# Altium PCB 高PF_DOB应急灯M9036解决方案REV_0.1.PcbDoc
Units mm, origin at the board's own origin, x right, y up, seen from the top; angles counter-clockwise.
Board outline 152.4 x 101.6 mm, 2 copper layers (Top Layer, Bottom Layer); 44 components, 28 nets, 116 pads, 0 vias.
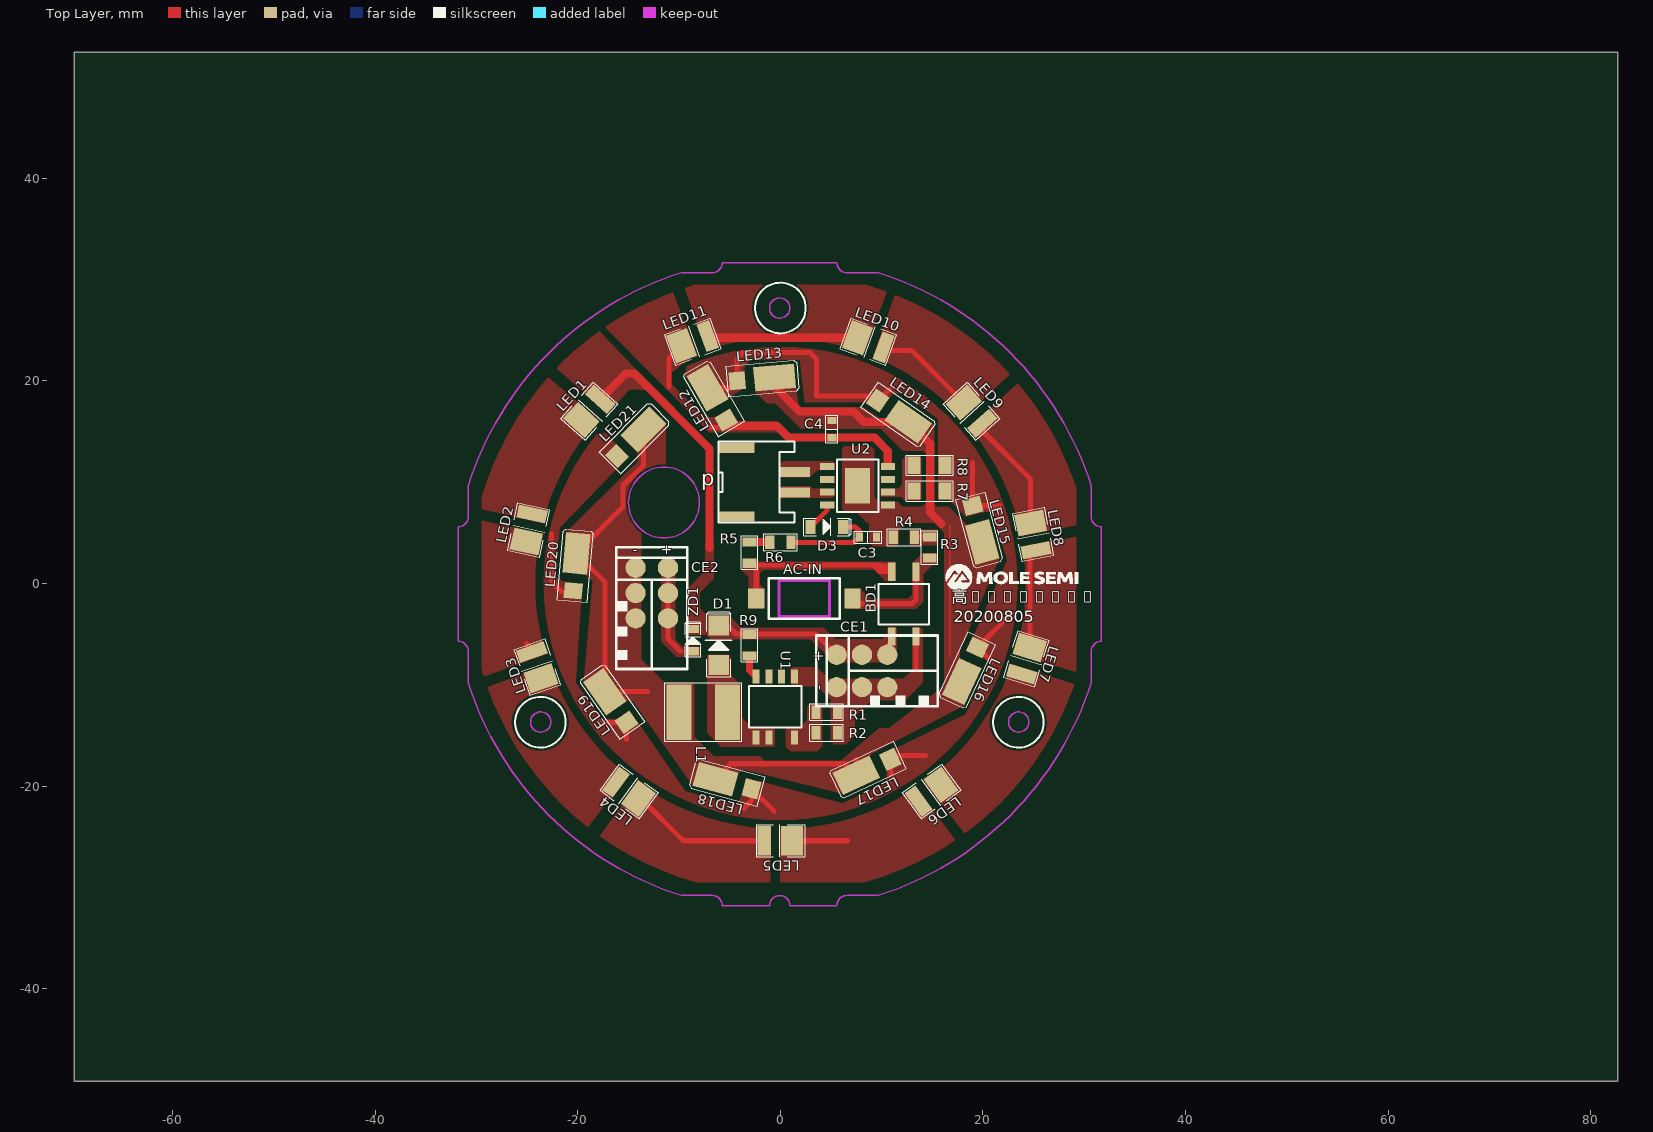
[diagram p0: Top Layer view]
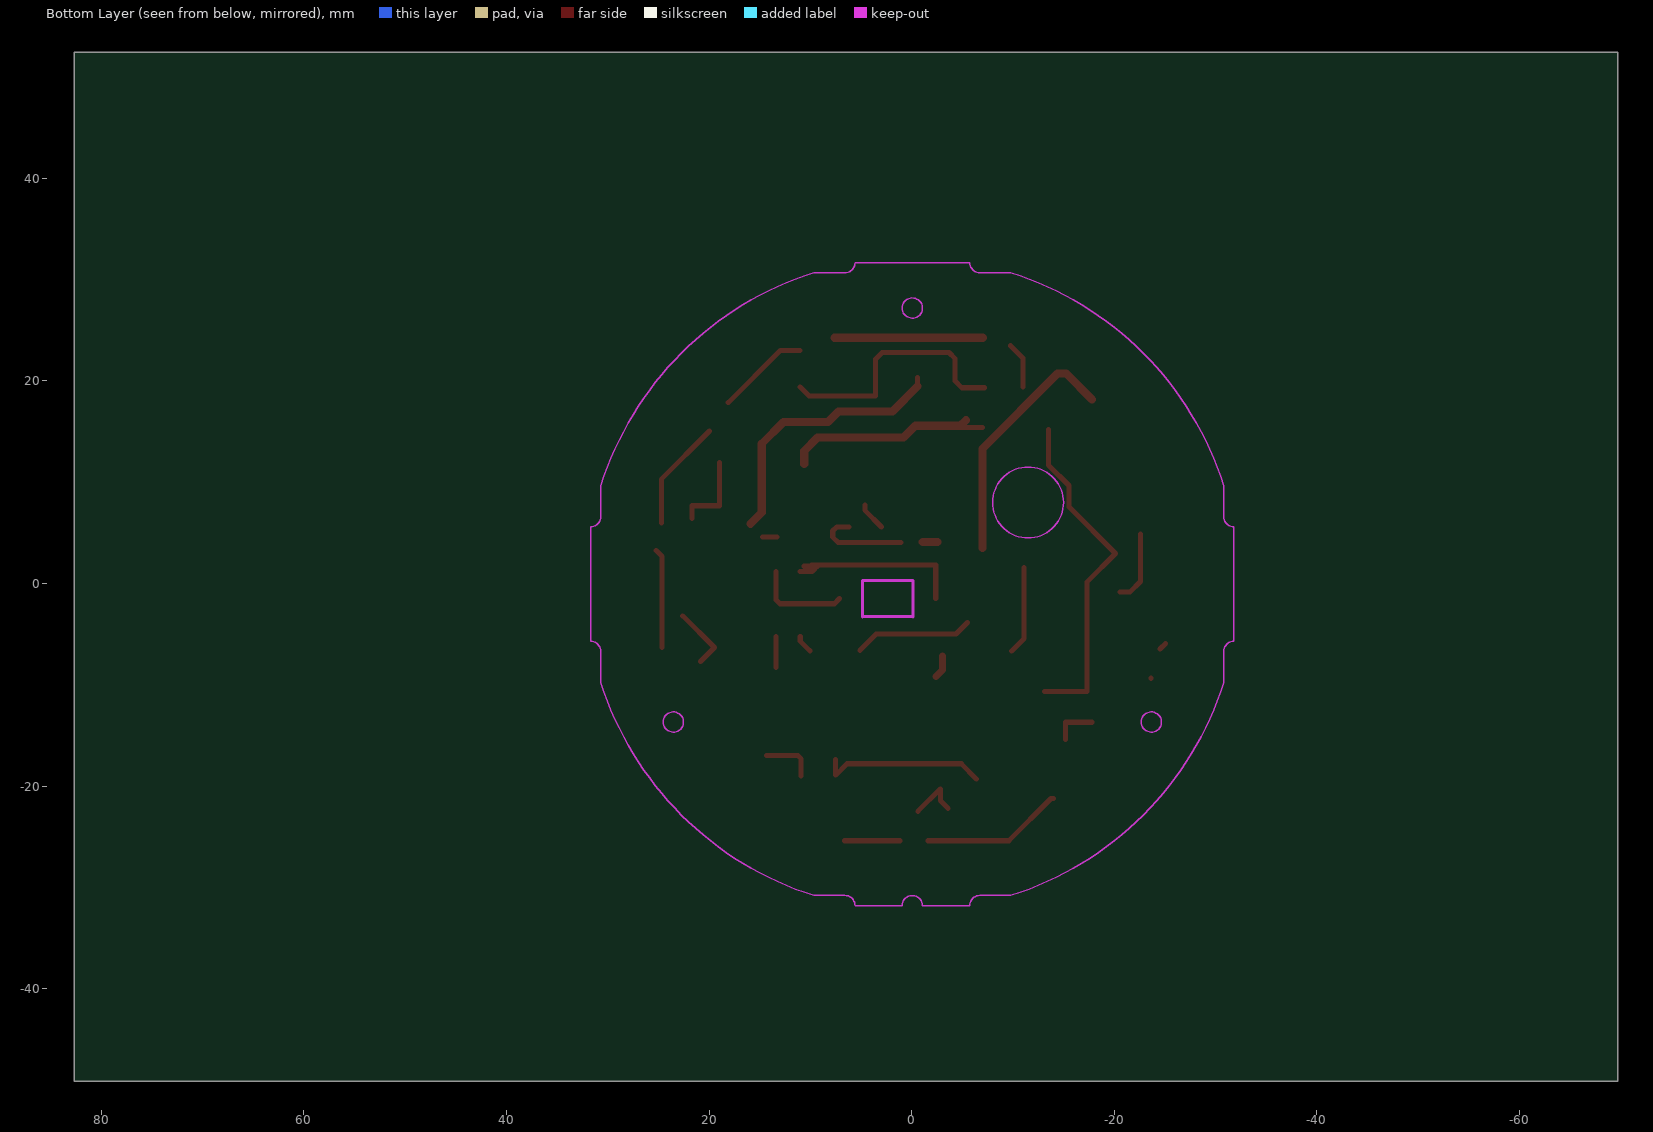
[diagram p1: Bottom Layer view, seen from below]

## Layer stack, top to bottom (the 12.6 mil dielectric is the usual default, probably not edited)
Top Solder: solder mask 0.0102, Solder Resist, Dk 3.5
Top Layer: signal copper 0.0356
Dielectric1: dielectric 0.32, FR-4, Dk 4.8
Bottom Layer: signal copper 0.0356
Bottom Solder: solder mask 0.0102, Solder Resist, Dk 3.5

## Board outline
-69.723,-49.149 82.677,-49.149 82.677,52.451 -69.723,52.451

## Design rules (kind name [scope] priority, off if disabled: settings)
Clearance [All] p1: gap=0.2 ignorepadtopadclearanceinfootprint=FALSE except(0: Arc-Hole Track-Hole SMDPad-Hole THPad-Hole Via-Hole Fill-Hole Poly-Hole Region-Hole Text-Hole)
ComponentClearance [All] p1 off: gap=0.254 collisioncheckmode=3 verticalgap=0.254 showdistances=FALSE
PlaneConnect [All] p1: planeconnectstyle=Direct reliefexpansion=0.508 reliefentries=4 reliefconductorwidth=0.254 reliefairgap=0.254
PolygonConnect [All] p1: connectstyle=Direct reliefconductorwidth=0.254 reliefentries=4 polygonreliefangle="90 Angle" airgapwidth=0.254
RoutingVias [All] p1: holewidth=0.711 width=1.27 viastyle="Through Hole" minholewidth=0.711 minwidth=1.27 maxholewidth=0.711 maxwidth=1.27
SilkToSolderMaskClearance SilkscreenOverComponentPads [IsPad] p1: minsilkscreentomaskgap=0.254 clearancetoexposedcopper=TRUE
SolderMaskExpansion [All] p1: expansion=0.102
Width [All] p1: maxlimit=1 minlimit=0.1 preferedwidth=0.5
27 further rules are at their usual default settings.

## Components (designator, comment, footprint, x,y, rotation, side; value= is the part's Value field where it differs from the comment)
AC-IN "Comment" AC-N 2.364,-1.492 r0 top
BD1 "MB10F" D-BRIDGE-C 12.192,-2.032 r0 top
C3 "104" 1608 8.636,4.572 r0 top
CE1 "2.2uF/400V" C-5.5/10.0L 3.556,-8.636 r90 top (schematic designator CE2)
CE2 "2.2uF/400V" C-5.5/10.0L -12.7,3.556 r0 top
D1 "ES1J" SMA -6.096,-6.096 r270 top
D3 "4.7V" SOD123 4.572,5.588 r0 top (schematic designator ZD1)
L1 "3.3mH/0810" L-6.0 -7.62,-12.7 r180 top
LED1 "D(LED)" LED-3528 -18.876,16.996 r228 top
LED2 "D(LED)" LED-3528 -24.845,5.281 r258 top
LED3 "D(LED)" LED-3528 -24.016,-8.269 r289 top
LED4 "D(LED)" LED-3528 -14.93,-20.549 r324 top
LED5 "D(LED)" LED-3528 0,-25.4 r0 top
LED6 "D(LED)" LED-3528 14.93,-20.549 r36 top
LED7 "D(LED)" LED-3528 24.29,-7.426 r73 top
LED8 "D(LED)" LED-3528 24.933,4.847 r101 top
LED9 "D(LED)" LED-3528 18.876,16.996 r132 top
LED10 "D(LED)" LED-3528 8.687,23.868 r160 top
LED11 "D(LED)" LED-3528 -8.687,23.868 r200 top
LED12 "D(LED)" LED-5630 -6.604,18.288 r120 top
LED13 "D(LED)" LED-5630 -1.771,20.243 r5 top
LED14 "D(LED)" LED-5630 11.655,16.645 r325 top
LED15 "D(LED)" LED-5630 19.628,5.259 r285 top
LED16 "D(LED)" LED-5630 18.416,-8.588 r245 top
LED17 "D(LED)" LED-5630 8.588,-18.416 r205 top
LED18 "D(LED)" LED-5630 -5.259,-19.628 r165 top
LED19 "D(LED)" LED-5630 -16.645,-11.655 r125 top
LED20 "D(LED)" LED-5630 -20.243,1.771 r85 top
LED21 "D(LED)" LED-5630 -14.368,14.368 r45 top
p "Comment" CN2-2.0-P -6.096,10 r90 top
R1 "3R6" 0805 4.572,-12.7 r0 top
R2 "3R3" 0805 4.572,-14.732 r0 top
R3 "2703" 0805 14.732,3.556 r90 top
R4 "2703" 0805 12.192,4.572 r180 top
R5 "2703" 0805 -3.048,3.048 r90 top
R6 "2703" 0805 0,4.064 r0 top
R7 "1R0" 1206 14.732,9.144 r0 top
R8 "1R0" 1206 14.732,11.684 r0 top
R9 "3R3" 0805 -3.048,-6.096 r90 top (schematic designator R2)
U1 "Comment" SOP7 -0.508,-12.192 r180 top
U2 "IC(M9036-8P)" SOP8N 7.62,9.652 r90 top
ZD1 "4.7V" SOD323 -8.636,-5.588 r90 top (schematic designator ZD2)
? "Comment" LOGO(M) 16.764,1.016 r0 top
? "Comment" 1608 5.08,15.24 r90 top

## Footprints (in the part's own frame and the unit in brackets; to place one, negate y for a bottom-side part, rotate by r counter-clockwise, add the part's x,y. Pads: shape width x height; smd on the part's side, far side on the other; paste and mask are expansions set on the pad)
0805 [mm]
  rect 0.9x1.35 smd: 1(-1.05,0) 2(1.05,0)
  silkscreen extent -1.65,-0.82 1.65,0.82
1206 [mm]
  rect 1.3x1.7 smd: 1(-1.525,0) 2(1.525,0)
  silkscreen extent -2.32,-1 2.32,1
1608 [mm]
  rect 0.7x0.9 smd: 1(-0.85,0) 2(0.85,0)
  silkscreen extent -1.35,-0.6 1.35,0.6
AC-N [mm]
  rect 1.6x2 smd: 1(-4.75,0) 2(4.75,0)
  silkscreen extent -3.5,-2 3.5,2
C-5.5/10.0L [mm]
  round 2 smd: 1(1.6,-2) 1(1.6,-7) 1(1.6,-4.5) 2(-1.6,-2) 2(-1.6,-7) 2(-1.6,-4.5)
  silkscreen extent -3.5,-12 3.5,0
CN2-2.0-P [mm]
  rect 1x3 smd: 1(1,-7.5) 2(-1,-7.5)
  rect 1x3.5 smd: ""(-3.4,-1.8) ""(3.4,-1.8)
  silkscreen extent -4,-7.5 4,0
D-BRIDGE-C [mm]
  round 0.9 on Top Overlay: 0(-1.75,-1.25)
  rect 0.7x1.8 smd: 1(-1.2,-3.2) 2(-1.2,3.2) 3(1.2,3.2) 4(1.2,-3.2)
  silkscreen extent -2.5,-2 2.5,2
L-6.0 [mm]
  rect 2.5x5.5 smd: 1(-2.4,0) 2(2.4,0)
  silkscreen extent -3.8,-2.9 3.8,2.9
LED-3528 [mm]
  rect 1.3x2.9 smd: 1(-1.6,0)
  rect 2.2x2.9 smd: 2(1.15,0)
  silkscreen extent -2.4,-1.6 2.4,1.6
LED-5630 [mm]
  rect 1.6x1.8 smd: 1(-2.5,0)
  rect 4.03x2.45 smd: 2(1.2,0)
  silkscreen extent -3.5,-1.5 3.5,1.5
LOGO(M) [mm]
  silkscreen extent -0.47,-1.67 12.62,0.87
SMA [mm]
  rect 2x2 smd: 1(1.95,0) 2(-1.95,0)
  silkscreen extent -3.3,-1.3 3.1,1.3
SOD123 [mm]
  rect 1x1.4 smd: 1(-1.6,0) 2(1.6,0)
  silkscreen extent -2.25,-0.85 2.4,0.85
SOD323 [mm]
  rect 0.8x1.2 smd: 1(-1.1,0) 2(1.1,0)
  silkscreen extent -1.65,-0.75 1.8,0.75
SOP7 [mm]
  round 0.9 on Top Overlay: 0(-1.905,-1.29)
  round 0.9 on Mech3: 0(-1.905,-1.29)
  rect 0.7x1.4 smd: 1(-1.905,-3) 2(-0.635,-3) 3(0.635,-3) 4(1.905,-3) 5(1.905,3) 6(0.635,3) 8(-1.905,3)
  silkscreen extent -2.6,-2.05 2.6,2.04
SOP8N [mm]
  round 0.9 on Top Overlay: 0(-3,-3) 0(-1.905,-1.29)
  round 0.9 on Mech3: 0(-1.905,-1.29)
  rect 3.5x2.5 smd: 0(0,0)
  rect 0.7x1.4 smd: 1(-1.905,-3) 2(-0.635,-3) 3(0.635,-3) 4(1.905,-3) 5(1.905,3) 6(0.635,3) 7(-0.635,3) 8(-1.905,3)
  silkscreen extent -2.6,-2.05 2.6,2.04

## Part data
BD1: library part D(B-DIODE), "DIODE"
C3: library part C, "CAPACITOR"
CE1 CE2: library part C(DIP), "CAPACITOR"
D1: library part D(DIODE), "DIODE"
D3 ZD1: library part D(ZENER), "DIODE"
L1: library part L(IND), "INDUCTOR"
LED1 LED2 LED3 LED4 LED5 LED6 LED7 LED8 LED9 LED10 LED11 LED12 LED13 LED14 LED15 LED16 LED17 LED18 LED19 LED20 LED21: "LED"
R1 R2 R3 R4 R5 R6 R7 R8 R9: library part R, "RESISTOR"
U2: library part IC(9031-8P)_1, "IC"

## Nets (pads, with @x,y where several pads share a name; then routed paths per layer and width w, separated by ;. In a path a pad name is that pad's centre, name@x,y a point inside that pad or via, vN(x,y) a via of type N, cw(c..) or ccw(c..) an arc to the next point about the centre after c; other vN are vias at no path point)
ACL: D3.1 U2.8 | length 2.8
  Top Layer w0.5: D3.1 4.62,7.236 U2.8
AGND: BD1.4 CE1.2 R1.2 R2.2 U1.1 | length 3.1
  Top Layer w0.5: 13.392,-8.3 BD1.4
GND: ?.2 C3.2 CE2.2 L1.2 LED13.2 LED14.2 LED15.2 LED16.2 LED17.2 LED18.2 LED19.2 LED20.2 LED21.2 R4.2 U2.0@7.62,9.652 U2.1 | length 77.5
  Top Layer w0.5: LED21.2 -13.52,11.684 -15.533,9.67 -15.533,7.572 LED20.2 -17.333,0.162 LED19.2 -13.128,-10.672 ; LED18.2 -4.901,-17.8 6.377,-17.8 LED17.2 7.5,-17.4 ; LED13.2@-0.576,19.476 LED13.2
  Top Layer w0.8: LED13.2@-0.576,19.476 1.9,17 7.2,17 8.243,15.957 LED14.2 14.8,13.795 14.8,7 15.9,5.9
NetBAT_1: p.2 U2.7
NetBAT_2: p.1 U2.5
NetBD1_1: BD1.1 CE1.1 D1.2 LED1.1 R9.2 ZD1.2 | length 38.3
  Top Layer w0.5: D1.2@-5.525,-3.846 -4.375,-4.996 3.496,-4.996 CE1.1@5.1,-6.6 ; CE1.1@10.048,-6.644 10.992,-5.7 BD1.1
  Top Layer w0.8: LED1.1 -15.272,20.718 -14.418,20.718 -7,13.3 -7,3.504
NetBD1_2: AC-IN.1 BD1.2 R5.1 | length 21.4
  Top Layer w0.5: AC-IN.1 -2.386,1.844 8,1.844 ; 9.3,1.7 9.9,1.7 ; 9.856,1.844 9.156,1.844 ; 10.4,1.7 9.9,1.7 ; 10.6,1.7 9.9,1.7 ; BD1.2 9.832,1.168 9.6,1.4 9.156,1.844 ; 8,1.844 8.4,1.844 ; 8,1.844 8.4,1.844 ; 8.4,1.844 9.156,1.844 ; 8.4,1.844 9.156,1.844 ; 8.4,1.844 9.156,1.844
NetBD1_3: AC-IN.2 BD1.3 R3.1 | length 9.4
  Top Layer w0.5: AC-IN.2 7.622,-2 13,-2 13.392,-1.608 BD1.3
NetC3_1: C3.1 D3.2 R6.2 | length 9.4
  Top Layer w0.5: R6.2 7.278,4.064 C3.1 7.786,5.158 7.8,5.172 7.384,5.588 D3.2
NetD1_1: D1.1 L1.1 U1.5 U1.6
NetLED1_2: LED1.2 LED2.1
NetLED2_2: LED2.2 LED3.1 | length 0.8
  Top Layer w0.5: -25.084,-5.916 LED3.1@-24.537,-6.463
NetLED3_2: LED3.2 LED4.1 | length 0
  Top Layer w0.5: LED3.2 LED3.2
NetLED4_2: LED4.2 LED5.1 | length 14.1
  Top Layer w0.5: LED4.2 -13.775,-21.225 -9.6,-25.4 LED5.1
NetLED5_2: LED5.2 LED6.1 | length 5.4
  Top Layer w0.5: LED5.2 6.6,-25.4
NetLED6_2: LED6.2 LED7.1
NetLED7_2: LED7.2 LED8.1 | length 9.9
  Top Layer w0.5: LED7.2 24.626,2.664 LED8.1
NetLED8_2: LED8.2 LED9.1 | length 11.1
  Top Layer w0.5: LED9.1@19.946,15.054 24.714,10.286 LED8.2
NetLED9_2: LED9.2 LED10.1 | length 9.2
  Top Layer w0.5: 11,23 12.957,23 LED9.2
NetLED10_2: LED10.2 LED11.1 | length 14.6
  Top Layer w0.8: LED11.1@-7.03,24.262 LED10.2
NetLED11_2: ?.1 LED11.2 LED12.1 U2.4 | length 29.7
  Top Layer w0.5: -11,19.4 -11,22.243 LED11.2 ; -7,15.4 -0.4,15.4
  Top Layer w0.8: LED12.1 -4.831,15.6 -0.4,15.6 0.8,14.4 9.3,14.4 10.6,13.1 U2.4@10.6,11.8
NetLED12_2: LED12.2 LED13.1 LED14.1 LED15.1 LED16.1 LED17.1 LED18.1 LED19.1 LED20.1 LED21.1 R7.2 R8.2 | length 61.8
  Top Layer w0.5: -22.6,4.9 -22.6,0.2 -21.541,-0.859 LED20.1@-20.6,-0.859 ; -17.8,-13.703 LED19.1 -15.211,-15.389 ; LED12.2 -4.959,19.327 -4.3,19.986 -4.3,22.2 -3.7,22.8 2.9,22.8 3.556,22.144 3.556,18.525 10.125,18.525 11,19.4 ; -3.6,-22.2 -2.844,-21.444 LED18.1 -0.619,-22.5 ; 10.9,-19 10.9,-17.313 11.213,-17 14.348,-17 ; 18.981,11.919 LED15.1 21.674,7.674 21.674,6.426 ; 20.851,-7.7 LED16.1 22.6,-3.195
NetR1_1: R1.1 R2.1 U1.8
NetR3_2: R3.2 R4.1 | length 1.5
  Top Layer w0.5: R4.1@13.276,4.606 R3.2
NetR5_2: R5.2 R6.1 | length 1.4
  Top Layer w0.8: R5.2@-2.54,4.098 R6.1@-1.1,4.098
NetR7_1: R7.1 R8.1 U2.2
NetU1_3: CE2.1 ZD1.1 | length 8.8
  Top Layer w0.5: CE2.1@-11.1,1.556 -11.1,-5.45 -9.862,-6.688
R9-2: R9.1 U1.4 | length 2.3
  Top Layer w0.7: R9.1 -3.048,-8.557 U1.4
pads on no net: BD1.0 p. U1.0 U1.2 U1.3 U2.0@8.91,7.747 U2.0@10.62,6.652 U2.3 U2.6

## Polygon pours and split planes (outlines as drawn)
NetR7_1 on Top Layer "ds" (solid, remove dead copper, pour order 1029): 12.5,10.1 12.55,10.05 13.9,10.05 13.9,8.325 13.825,8.25 13.775,8.2 12.825,8.2 12.3,8.2 11.9,8.6 11.85,8.65 11.35,8.65 11.35,8.975
GND on Top Layer "ds" (solid, remove dead copper, pour order 1041): -2.4,19.2 -2.465,19.027 -2.475,18.95 -1.325,17.8 -0.5,17.8 2,15.3 9.9,15.3 12.1,13.1 14.8,13.1 15.2,13.5 15.2,15.6 14.9,15.9 14.8,15.8 11.7,15.8 11.2,16.3 9.8,16.3 8.2,17.4 1.8,17.4 1.4,20.1 0.4,20.1
AGND on Top Layer "ds" (solid, remove dead copper, pour order 1050): 13.275,-4.325 13.625,-4.325 13.875,-4.325 14,-4.45 14.075,-4.525 14.075,-5.8 14.075,-9.8 13.175,-10.7 12.325,-11.55 9.775,-11.55 8.95,-11.55 7.9,-12.6 7.325,-13.175 7.325,-14.35 7.325,-15.025 6.55,-15.8 6.475,-15.875 5.375,-15.875 5.268,-15.875 4.95,-15.557 4.95,-13.525 4.95,-11.469 4.556,-11.075 3.623,-10.142 2.092,-10.142 1.267,-10.142 1,-9.875 0.975,-9.85 0.975,-8.425 1.1,-8.3 1.15,-8.25 1.5,-8.25 3.581,-8.25 4.556,-9.225 4.756,-9.425 6.756,-9.425 12.15,-9.425 12.675,-8.9 13,-8.575 13,-4.5 13,-4.425 13.1,-4.325
NetD1_1 on Top Layer "ds" (solid, remove dead copper, pour order 1047): -6.625,-7.025 -5.1,-7.025 -4.975,-7.15 -4.975,-8.975 -3.82,-10.13 -3.82,-13.262 -2.85,-14.232 -0.768,-14.232 -0.55,-14.45 -0.55,-16.025 -0.625,-16.1 -5.825,-16.1 -7.2,-14.725 -7.2,-7.15 -7.097,-7.046
NetU1_3 on Top Layer "ds" (solid, remove dead copper, pour order 1044): -11.675,2.556 -10.606,2.556 -10.375,2.325 -10.375,-5.55 -9.75,-6.175 -9.7,-6.225 -8.675,-6.225 -7.986,-6.225 -7.886,-6.325 -7.886,-6.95 -7.886,-7.024 -8.1,-7.238 -8.112,-7.25 -10.25,-7.25 -10.275,-7.25 -11.625,-5.9 -11.775,-5.75 -11.775,-1.25 -11.775,2.306 -11.525,2.556
NetBD1_1 on Top Layer "ds" (solid, remove dead copper, pour order 1040): 10.625,-4.325 11.4,-4.325 11.475,-4.4 11.475,-7.425 11.1,-7.8 5.275,-7.8 3,-5.525 -6.896,-5.525 -7.396,-5.025 -7.409,-5.038 -9.037,-5.038 -9.2,-4.875 -9.2,-0.55 -7.4,1.25 -7.4,4.225 -7.2,4.225 -7,4.425 -6.675,4.1 -6.6,4.1 -6.6,0.45 -7.983,-0.933 -7.975,-0.941 -7.975,-2.45 -7.279,-3.146 -5.079,-3.146 -3.875,-4.35 4.302,-4.35 5.452,-5.5 10.036,-5.5 10.55,-4.986 10.55,-4.4
NetR1_1 on Top Layer "ds" (solid, remove dead copper, pour order 1037): 0.85,-14.232 1.825,-14.232 1.893,-14.232 2.475,-13.65 2.65,-13.475 2.65,-12.65 2.65,-12.147 2.922,-11.875 3.95,-11.875 4.15,-12.075 4.15,-12.775 4.15,-16.05 3.825,-16.375 3.65,-16.55 2.075,-16.55 1,-16.55 0.65,-16.2 0.55,-16.1 0.55,-15.275 0.55,-14.432 0.75,-14.232
GND on Top Layer "ds" (solid, remove dead copper, pour order 1052): 16.2,5.2 16.2,-10.1 10.7,-14.3 9.775,-14.3 5.975,-17.5 -1.6,-17.5 -2.05,-17.05 -7.175,-17.05 -13.725,-7.9 -13.725,8.65 -14.4,11.6 -14.6,11.6 -21.2,5 -21.2,1.7 -20,1.7 -17.7,-0.6 -17.7,-10.4 -16.4,-10.4 -15.2,-11.6 -14.6,-11.6 -8.6,-20 -4.2,-18.7 -3.5,-18.4 6.3,-20.8 8.6,-17.2 8.8,-17 9.4,-16.3 10.3,-16.1 18.2,-12 17.7,-7.4 17.7,-6.6 21.6,2.5 17.9,5.8
GND on Top Layer "ds" (solid, remove dead copper, pour order 1033): -16.2,-2.525 -16.075,-2.65 -13.825,-2.65 -13.825,-7.395 -11.42,-9.8 -8.9,-9.8 -8.65,-9.8 -8.5,-9.95 -8.5,-12.775 -8.5,-15.15 -6.6,-17.05 -6.025,-17.625 -5.3,-17.625 -5.3,-19.95 -5.275,-19.975 -6.399,-18.851 -8.675,-18.851 -8.675,-16.825 -13.35,-12.15 -15.3,-10.2 -15.3,-9.25
GND on Top Layer "ds" (solid, remove dead copper, pour order 1046): 6.325,13.55 8.9,13.55 9.2,13.25 9.25,13.2 9.25,9.025 9.25,8.497 9.695,8.052 9.697,8.05 11.25,8.05 11.575,8.05 12.05,7.575 11.7,7.225 11.7,6.125 11.7,3.997 11.45,3.747 11.403,3.7 9.175,3.7 8.75,4.125 8.75,5.4 8.75,5.825 8.35,6.225 7.523,7.052 6.825,7.052 6.448,7.052 6.175,7.325 6.1,7.4 6.1,13.325
NetR7_1 on Top Layer "ds" (solid, remove dead copper, pour order 1043): 9.904,8.667 9.997,8.575 11.575,8.575 13.75,8.575 13.875,8.7 13.9,8.725 13.9,12.075 13.9,12.384 13.8,12.484 13.734,12.55 12.407,12.55 12.375,12.55 12.15,12.325 12.05,12.225 12.05,9.9 12.05,9.775 11.825,9.55 11.642,9.367 9.904,9.367
NetBAT_1 on Top Layer "ds" (solid, remove dead copper, pour order 1039): -0.096,9.375 -0.096,8.475 5.112,8.475 5.304,8.667 5.325,8.688 5.325,9.312 5.325,9.347 5.304,9.367 5.297,9.375 3.375,9.375 3.175,9.375 2.95,9.6 0.15,9.6 0.129,9.6 -0.096,9.375
NetBAT_2 on Top Layer "ds" (solid, remove dead copper, pour order 1036): -0.096,10.65 -0.096,11.704 0.2,12 0.25,12.05 4.3,12.05 5.177,12.05 5.32,11.907 5.35,11.877 5.35,11.252 3.965,11.252 3.92,11.207 3.913,11.2 3.65,11.2 3.6,11.2 3.3,10.9 2.9,10.5 2.625,10.5 0.004,10.5 -0.096,10.6
GND on Top Layer "ds" (solid, remove dead copper, pour order 1054): 12,-15.2 8.3,-17.2 7.9,-19.4 6.2,-18.6 7.7,-16.4
NetBD1_3 on Top Layer "ds" (solid, remove dead copper, pour order 1049): 6.6,-2.5 13.1,-2.5 13.4,-2.5 14,-1.9 14.1,-1.8 14.1,0.8 14.1,0.9 15,1.8 15.1,1.9 15.5,1.9 15.5,2.9 15.4,3 14.1,3 14,3 13.1,2.1 13,2 13,-0.7 13,-1.1 12.6,-1.5 9.1,-1.5 8.9,-1.5 7.9,-0.5 6.5,-0.5
NetLED12_2 on Top Layer "ds" (solid, remove dead copper, pour order 1032): 1.9,22.4 2.4,17.9 8.4,17.9 10.8,18.329 11.3,18.971
NetBD1_1 on Top Layer "ds" (solid, remove dead copper, pour order 1070): -17.1,16.8 -22.5,21.6 -18.1,25.1 -13,19.8 -13.1,19.1 -14.9,19.2 -16.9,17
NetLED11_2 on Top Layer "ds" (solid, remove dead copper, pour order 1069): -8.2,22.5 -10.8,29.2 -15.4,27.1 -16.3,26.4 -16.8,26.1 -16.9,25.9 -17.2,25.7 -17.4,25.5 -17.5,25.5 -7,14.9 0.074,14.926 -0.4,15.4 -3.8,15.4 -4.9,17 -6.5,16.4 -7.4,16.4 -10.8,19.7 -10.8,20.8 -8.3,22.7
GND on Top Layer "ds" (solid, remove dead copper, pour order 1068): -21.051,4.946 -14.1,12 -14.1,14.9 -11.301,15.686 -11.3,11.7
GND on Top Layer "ds" (solid, remove dead copper, pour order 1067): -18.5,0.8 -19.4,-9.8 -16.7,-11.4 -17.1,0.8
NetLED12_2 on Top Layer "ds" (solid, remove dead copper, pour order 1066): 20.851,-7.7 18.3,-12.9 11.1,-16.4 10.5,-18.5 10.48,-19.42 10.5,-19.7 6.1,-21.7 -2.2,-19.5 -3.8,-20.9 -4.3,-21.9 -9.4,-20.5 -14.1,-13.7 -15.1,-13.5 -17.6,-13.5 -20.2,-9.8 -19.6,-0.3 -21.2,0.1 -22.3,0.6 -21.8,5.5 -15,12.5 -17.3,14.9 -18.5,14.8 -22.2,8.8 -23.9,1.9 -23.1,-6.2 -20.4,-12.4 -15.3,-18.7 -6.2,-23.2 4.1,-23.8 15,-19.4 21.2,-11.3 22.5,-8
GND on Top Layer "ds" (solid, remove dead copper, pour order 1065): 16.7,5.8 16.7,-5.2 16.7,-7.3
GND on Top Layer "ds" (solid, remove dead copper, pour order 1064): 10.8,7.6 13.3,7.6 13.1,6.5 11.2,6.5
NetLED12_2 on Top Layer "ds" (solid, remove dead copper, pour order 1063): 20.8,7.4 22.4,2.3 18.5,-6.5 20.5,-7.6 22,-8.2 23.7,-3.7 23.8,2.7 22.2,8.4
NetLED12_2 on Top Layer "ds" (solid, remove dead copper, pour order 1062): -3.52,21.454 -3,22.1 1.9,22.1 2.7,21.3 3.051,23.173 -4,23.3
NetLED12_2 on Top Layer "ds" (solid, remove dead copper, pour order 1061): 10.756,19.156 10.8,18.8 12,18.8 15.8,16.1 18.4,6.8 22.3,7.8 19.8,13.3 14.7,19.4 11.5,20.5
NetLED12_2 on Top Layer "ds" (solid, remove dead copper, pour order 1060): -9.4,20.5 -9.2,21.8 -4.6,23.3 1.2,23.7 7.3,22.5 10.5,21.3 11.6,20.5 12.1,20.2 9.7,17 8.4,17.9 2.7,18 2.6,19.3 2.6,22.2 2,22.5 -3.1,22.5 -3.5,22 -3.6,19.3 -6.8,17.3
NetLED10_2 on Top Layer "ds" (solid, remove dead copper, pour order 1059): 8.1,22.5 10.6,29.1 8.5,29.8 -9.6,29.6 -7.2,22.7
NetLED9_2 on Top Layer "ds" (solid, remove dead copper, pour order 1058): 17.8,16.1 22.9,20.9 16.2,26.6 11.4,28.8 9.1,22.2
NetLED8_2 on Top Layer "ds" (solid, remove dead copper, pour order 1057): 23.4,4.6 29.5,5.8 29.5,9.7 26.2,17.1 23.9,19.8 23.7,20 18.5,15.2
NetLED7_2 on Top Layer "ds" (solid, remove dead copper, pour order 1056): 22.9,-6.9 29.7,-8.9 29.5,5.1 29.5,4.7 23.7,3.5
NetLED6_2 on Top Layer "ds" (solid, remove dead copper, pour order 1055): 14,-19.4 18.5,-25 25.1,-18.7 29.3,-10 22.6,-7.9
NetLED5_2 on Top Layer "ds" (solid, remove dead copper, pour order 1053): 0,-23.9 0,-29.8 10.4,-29.7 17.6,-25.8 13.1,-19.8
NetLED4_2 on Top Layer "ds" (solid, remove dead copper, pour order 1051): -13.9,-19.4 -18,-25.2 -12.2,-28.5 -7,-30.4 -1,-29.8 -1,-23.8
NetLED3_2 on Top Layer "ds" (solid, remove dead copper, pour order 1048): -22.6,-7.9 -29.1,-10.3 -26.2,-17.6 -20.2,-23.9 -19.2,-24.3 -14.9,-18.7
NetLED2_2 on Top Layer "ds" (solid, remove dead copper, pour order 1045): -23.4,4.9 -30,6.3 -29.8,-9 -29.6,-9.3 -22.9,-6.9
NetLED1_2 on Top Layer "ds" (solid, remove dead copper, pour order 1042): -17.8,16 -23.2,20.6 -27.3,15.1 -29.3,9.9 -29.8,7.4 -23.2,5.9
NetR3_2 on Top Layer "ds" (solid, remove dead copper, pour order 1035): 12.8,5.3 15.4,5.3 15.5,5.2 15.5,4.2 15.5,3.9 15.4,3.8 12.9,3.8 12.7,4 12.7,5.2
GND on Top Layer "ds" (solid, remove dead copper, pour order 1034): 14,7.6 14.7,8.3 15.4,7.6 16.6,7.6 18.6,5.6 18.6,5 16.2,5 15.2,6 12.4,6 11.6,5.2 10.4,5.2 10.4,7.6
NetLED12_2 on Top Layer "ds" (solid, remove dead copper, pour order 1038): 15.6,8.3 16.6,8.3 18.3,6.6 20.3,7.1 21,7.1 21,9.6 19.8,10.8 17.7,12.9 17.7,14.1 17.7,14.9 15.6,17 15.6,12.4
NetBD1_2 on Top Layer "ds" (solid, remove dead copper, pour order 1031): -1.625,-2.492 -1.6,-2.467 -1.6,-0.5 -2.025,-0.075 -2.025,1.025 -1.675,1.375 9.25,1.375 10.375,0.25 11.375,0.25 11.375,2.025 11.225,2.175 11.2,2.15 -3.571,2.15 -3.725,1.996 -3.725,1.2 -3.134,0.609 -3.134,-2.442
GND on Top Layer "ds" (solid, remove dead copper, pour order 1030): 13.475,16.575 14.8,13.9 14.8,12.559 14.725,12.484 13.9,13.309 12.659,14.111 11.3,16.6

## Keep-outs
Keep-Out Layer:
  circle w0.127: c-11.5,8 r3.5
  circle w0.127: c23.528,-13.682 r1
  circle w0.127: c-23.671,-13.682 r1
  circle w0.127: c-0.072,27.193 r1
  lines w0.127: -31.822,-5.713 cw(c-31.822,-6.713) -30.822,-6.713 -30.822,-9.778 ccw(c-0.072,-0.057) -9.793,-30.807 -6.728,-30.807 cw(c-6.728,-31.807) -5.728,-31.807 -1.072,-31.807 cw(c-0.072,-31.807) 0.928,-31.807 5.585,-31.807 cw(c6.585,-31.807) 6.585,-30.807 9.65,-30.807 ccw(c-0.072,-0.057) 30.678,-9.778 30.678,-6.713 cw(c31.678,-6.713) 31.678,-5.713 31.678,5.6 cw(c31.678,6.6) 30.678,6.6 30.678,9.665 ccw(c-0.072,-0.057) 9.65,30.693 6.585,30.693 cw(c6.585,31.693) 5.585,31.693 -5.728,31.693 cw(c-6.728,31.693) -6.728,30.693 -9.793,30.693 ccw(c-0.072,-0.057) -30.822,9.665 -30.822,6.6 cw(c-31.822,6.6) -31.822,5.6 -31.822,-5.713
  lines w0.3: -0.15,-3.3 -0.15,0.308 ; -0.136,-3.278 4.864,-3.278 ; -0.136,0.308 4.864,0.308 ; 4.85,-3.3 4.85,0.308

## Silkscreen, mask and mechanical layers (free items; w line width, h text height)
Top Overlay:
  circle w0.2: c23.5,-13.7 r2.5
  circle w0.2: c-23.7,-13.7 r2.5
  circle w0.2: c0,27.2 r2.5
  text "C4" at 2.35,15.3 h1
  text "高PF_M9036" at 16.9,-2.275 h2
  text "20200805" at 17.125,-4.225 h2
